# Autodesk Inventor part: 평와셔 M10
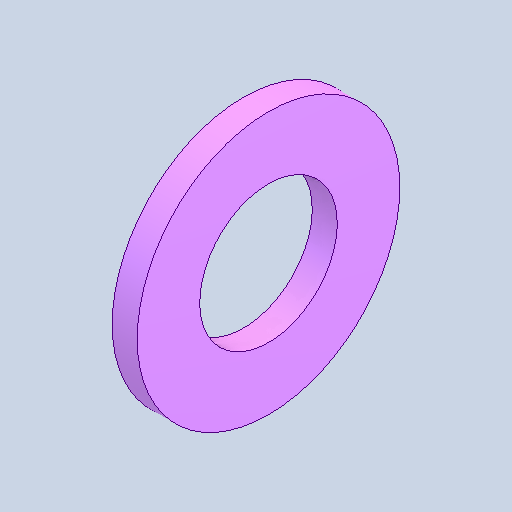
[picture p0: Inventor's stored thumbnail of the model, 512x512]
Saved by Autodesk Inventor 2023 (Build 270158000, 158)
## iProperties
Created: 2024-09
Part Number: 평와셔 M10
Material: 강철, 연강
Description: 평면 와셔
Document SubType Name: Modeling
Designer: home
Density: 7.85 g/cm^3
Appearance: 기본값
Author: jhkim
Sending System: Autodesk Inventor 2025
Preprocessor: ST-DEVELOPER v20
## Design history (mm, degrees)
node "평와셔 M101"
node "솔리드1"
body "Solid1"
